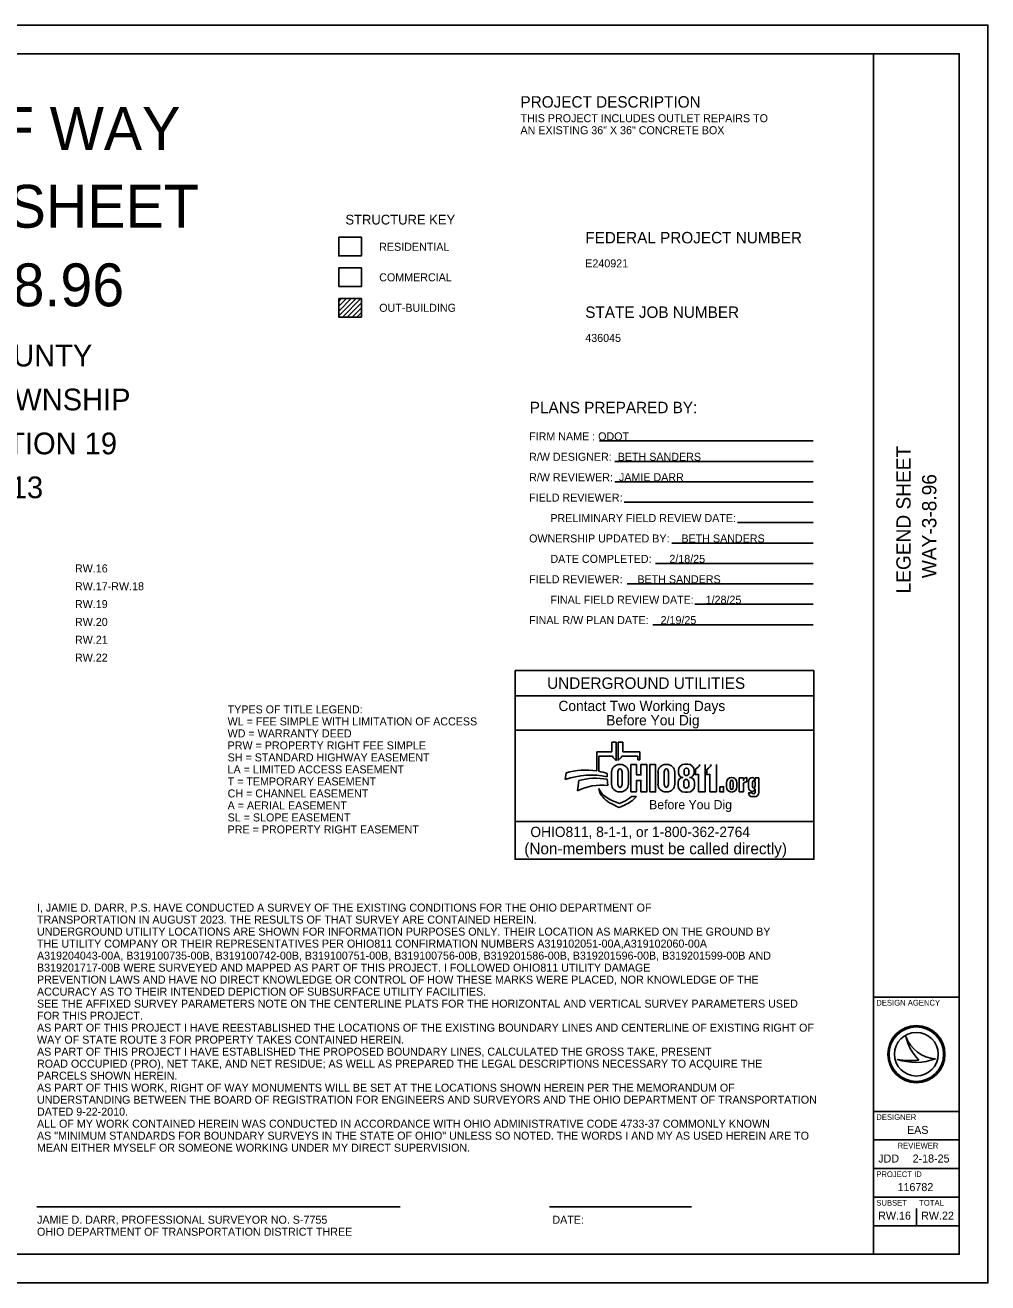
# Model space of a CAD drawing. Extents: x 0 to 34, y 0 to 22.
# Drawn here: x 17.17 to 34, y 0 to 22 of the extents above; entities that cross this region are included whole.
import ezdxf

# ---------------------------------------------------------------- set-up
doc = ezdxf.new("R2010")
doc.units = 0
for name, color, linetype in [('Default', 7, 'Continuous'), ('SC_Shading1', 7, 'Continuous'), ('SH_Border', 7, 'Continuous'), ('SH_Cut_Line', 7, 'Continuous'), ('SH_Data', 7, 'Continuous'), ('SH_Text', 7, 'Continuous')]:
    doc.layers.add(name, color=color, linetype=linetype)

msp = doc.modelspace()

# ---------------------------------------------------------------- linework, layer by layer
at = {"layer": 'Default'}
for p, q in [((17.374, 1.33), (23.727, 1.33)), ((26.334, 1.33), (28.821, 1.33))]:
    msp.add_line(p, q, dxfattribs=at)
at = {"layer": 'SC_Shading1'}
msp.add_lwpolyline([(22.649, 17.428), (23.046, 17.428), (23.046, 17.754), (22.649, 17.754)], close=True, dxfattribs=at)
at = {"layer": 'SH_Border'}
for p, q in [((32, 0.5), (32, 21.5)), ((32, 5), (33.5, 5)), ((32, 3), (33.5, 3)), ((32, 2.5), (33.5, 2.5)), ((32, 2), (33.5, 2)), ((32, 1.5), (33.5, 1.5)), ((32, 1), (33.5, 1))]:
    msp.add_line(p, q, dxfattribs=at)
msp.add_lwpolyline([(1.5, 21.5), (33.5, 21.5), (33.5, 0.5), (1.5, 0.5)], close=True, dxfattribs=at)
at = {"layer": 'SH_Cut_Line'}
msp.add_lwpolyline([(0, 0), (34, 0), (34, 22), (0, 22)], close=True, dxfattribs=at)
at = {"layer": 'SH_Data'}
for p, q in [((27.424, 9.289), (27.161, 9.289)), ((27.161, 9.289), (27.161, 8.954)), ((27.504, 9.455), (27.424, 9.455)), ((27.424, 9.455), (27.424, 9.289)), ((27.504, 9.138), (27.504, 9.455)), ((27.615, 9.455), (27.535, 9.455)), ((27.535, 9.455), (27.535, 9.138)), ((27.615, 9.289), (27.615, 9.455)), ((27.913, 9.289), (27.615, 9.289)), ((27.913, 9.148), (27.913, 9.289)), ((27.198, 8.948), (27.198, 9.212)), ((27.198, 9.212), (27.439, 9.212)), ((27.58, 9.067), (27.556, 9.067)), ((27.599, 9.212), (27.878, 9.212)), ((27.858, 9.066), (27.757, 9.066)), ((27.757, 9.066), (27.757, 8.588)), ((27.878, 9.212), (27.878, 9.148)), ((27.878, 9.148), (27.913, 9.148)), ((28.391, 9.067), (28.366, 9.067)), ((28.752, 9.074), (28.703, 9.074)), ((29.056, 9.066), (29.056, 8.588)), ((29.256, 9.066), (29.256, 8.588)), ((26.626, 8.92), (26.612, 8.803)), ((27.345, 8.852), (27.345, 8.91)), ((27.355, 8.702), (27.345, 8.808)), ((27.422, 8.934), (27.422, 8.722)), ((27.531, 8.739), (27.531, 8.921)), ((27.605, 8.921), (27.605, 8.739)), ((27.714, 8.722), (27.714, 8.934)), ((28.233, 8.934), (28.233, 8.722)), ((28.342, 8.739), (28.342, 8.921)), ((28.416, 8.921), (28.416, 8.739)), ((28.525, 8.722), (28.525, 8.934)), ((28.589, 8.96), (28.589, 8.924)), ((28.688, 8.907), (28.688, 8.965)), ((28.769, 8.965), (28.769, 8.907)), ((28.866, 8.924), (28.866, 8.96)), ((28.889, 8.886), (28.889, 8.987)), ((28.938, 8.588), (28.938, 8.9)), ((29.089, 8.886), (29.089, 8.987)), ((29.138, 8.588), (29.138, 8.9)), ((29.725, 8.831), (29.652, 8.831)), ((29.652, 8.831), (29.652, 8.588)), ((29.725, 8.784), (29.725, 8.831)), ((29.786, 8.839), (29.78, 8.839)), ((29.786, 8.765), (29.786, 8.839)), ((29.929, 8.786), (29.929, 8.833)), ((29.929, 8.833), (29.994, 8.833)), ((29.994, 8.833), (29.994, 8.574)), ((26.846, 8.785), (26.824, 8.605)), ((27.197, 8.648), (27.202, 8.621)), ((27.556, 8.588), (27.58, 8.588)), ((27.757, 8.588), (27.858, 8.588)), ((27.858, 8.588), (27.858, 8.79)), ((28.366, 8.588), (28.391, 8.588)), ((28.584, 8.753), (28.584, 8.703)), ((28.685, 8.694), (28.685, 8.755)), ((28.705, 8.582), (28.751, 8.582)), ((28.77, 8.755), (28.77, 8.694)), ((28.872, 8.703), (28.872, 8.753)), ((29.056, 8.588), (28.938, 8.588)), ((29.256, 8.588), (29.138, 8.588)), ((29.43, 8.679), (29.43, 8.747)), ((29.497, 8.678), (29.497, 8.747)), ((29.545, 8.747), (29.545, 8.678)), ((29.612, 8.747), (29.612, 8.679)), ((29.652, 8.588), (29.725, 8.588)), ((29.725, 8.588), (29.725, 8.715)), ((29.774, 8.765), (29.786, 8.765)), ((29.814, 8.666), (29.814, 8.77)), ((29.886, 8.68), (29.886, 8.756)), ((29.929, 8.756), (29.929, 8.68)), ((29.929, 8.574), (29.929, 8.644)), ((27.562, 8.387), (27.474, 8.418)), ((27.624, 8.414), (27.562, 8.387)), ((27.856, 8.508), (27.77, 8.508)), ((27.853, 8.505), (27.856, 8.508)), ((29.814, 8.574), (29.886, 8.574)), ((29.924, 8.505), (29.884, 8.505)), ((27.498, 8.341), (27.553, 8.317)), ((27.553, 8.317), (27.648, 8.358)), ((30.96, 7.41), (25.735, 7.41)), ((32.567, 4.31), (32.567, 4.31)), ((32.75, 4), (32.75, 4)), ((32.417, 3.91), (32.417, 3.91)), ((33.087, 3.919), (33.087, 3.919)), ((32.75, 1), (32.75, 1.3))]:
    msp.add_line(p, q, dxfattribs=at)
for points in [[(25.735, 10.71), (30.96, 10.71), (30.96, 10.27), (25.735, 10.27)], [(25.735, 10.27), (30.96, 10.27), (30.96, 9.665), (25.735, 9.665)], [(25.735, 9.665), (30.96, 9.665), (30.96, 8.07), (25.735, 8.07)], [(29.314, 8.678), (29.38, 8.678), (29.38, 8.588), (29.314, 8.588)], [(25.735, 8.07), (30.96, 8.07), (30.96, 7.41), (25.735, 7.41)]]:
    msp.add_lwpolyline(points, close=True, dxfattribs=at)
for points in [[(27.858, 8.79), (27.934, 8.79), (27.934, 8.588), (28.036, 8.588), (28.036, 9.066), (27.934, 9.066), (27.934, 8.886), (27.858, 8.886), (27.858, 9.066)], [(28.087, 8.588), (28.189, 8.588), (28.189, 9.066), (28.087, 9.066), (28.087, 8.588)], [(28.67, 8.84), (28.67, 8.84)], [(28.786, 8.84), (28.786, 8.84)]]:
    msp.add_lwpolyline(points, dxfattribs=at)
for radius in [0.5, 0.477, 0.477, 0.382]:
    msp.add_circle((32.75, 4), radius, dxfattribs=at)
for centre, radius, start, end in [((27.556, 8.934), 0.134, 90, 180), ((27.576, 9.267), 0.147, 201.9296, 240.7469), ((27.463, 9.267), 0.147, 299.2531, 338.0704), ((27.58, 8.934), 0.134, 0, 90), ((28.366, 8.934), 0.134, 90, 180), ((28.391, 8.934), 0.134, 0, 90), ((28.703, 8.96), 0.114, 90, 180), ((28.752, 8.96), 0.114, 0, 90), ((28.839, 9.109), 0.132, 292.5572, 340.7355), ((29.039, 9.109), 0.132, 292.5572, 340.7355), ((27.064, 7.55), 1.332, 77.8238, 109.8274), ((26.969, 7.746), 1.224, 81.0007, 106.3144), ((27.145, 7.733), 1.094, 79.44, 105.8467), ((26.969, 7.746), 1.224, 72.1402, 79.2074), ((28.67, 8.753), 0.0865, 90, 180), ((28.673, 8.924), 0.0837, 180, 268.1442), ((28.783, 8.924), 0.0837, 272.2058, 0), ((28.786, 8.753), 0.0865, 0, 90), ((28.877, 9.017), 0.132, 275.1733, 297.0931), ((29.077, 9.017), 0.132, 275.1733, 297.0931), ((29.525, 8.747), 0.0956, 92.5886, 180), ((29.517, 8.747), 0.0956, 0, 87.4114), ((29.78, 8.784), 0.0548, 90, 180), ((29.882, 8.77), 0.0686, 92.6865, 180), ((29.876, 8.786), 0.0524, 0, 86.9262), ((27.253, 7.758), 0.95, 83.8248, 116.8021), ((27.477, 8.756), 0.3, 201.0457, 232.5314), ((27.413, 8.657), 0.214, 189.6817, 216.0884), ((27.556, 8.722), 0.134, 180, 270), ((27.58, 8.722), 0.134, 270, 0), ((28.366, 8.722), 0.134, 180, 270), ((28.391, 8.722), 0.134, 270, 0), ((28.705, 8.703), 0.121, 180, 270), ((28.751, 8.703), 0.121, 270, 0), ((29.525, 8.679), 0.0956, 180, 267.4114), ((29.517, 8.679), 0.0956, 272.5886, 0), ((29.774, 8.715), 0.0493, 90, 180), ((29.883, 8.666), 0.0692, 180, 265.7132), ((29.882, 8.644), 0.0467, 264.7825, 0), ((27.613, 8.803), 0.461, 216.0884, 235.7167), ((27.765, 9.131), 0.773, 232.5314, 241.794), ((27.861, 9.168), 0.903, 235.7167, 246.2325), ((27.638, 8.894), 0.504, 241.794, 250.9821), ((27.41, 8.907), 0.538, 293.4582, 312.0712), ((27.41, 8.907), 0.599, 293.4582, 317.8286), ((29.884, 8.574), 0.0699, 180, 270), ((29.924, 8.574), 0.0699, 270, 0), ((33.116, 4.498), 0.58, 198.9257, 198.9319), ((33.347, 4.47), 0.796, 191.6379, 191.6421), ((33.116, 4.498), 0.58, 198.9319, 267.1657), ((33.347, 4.47), 0.796, 191.6421, 226.0947), ((32.739, 4.87), 1.013, 251.4576, 290.0832), ((32.648, 5.154), 1.266, 259.4964, 259.4995), ((32.739, 4.87), 1.013, 251.4527, 251.4576), ((32.648, 5.154), 1.266, 259.4995, 276.6672)]:
    msp.add_arc(centre, radius, start, end, dxfattribs=at)
for centre, major_axis, ratio, start_param, end_param in [((27.568, 8.921), (0, 0.0723), 0.514403, 4.712389, 7.853982), ((28.379, 8.921), (0, 0.0723), 0.514403, 4.712389, 7.853982), ((28.727, 8.755), (0, 0.0535), 0.794529, 4.712389, 7.853982), ((28.729, 8.965), (0.0404, 0), 0.969373, 0, 3.141593), ((28.729, 8.907), (0.0404, 0), 0.818453, 3.141593, 6.283185), ((27.568, 8.739), (0, 0.0723), 0.514403, 1.570796, 4.712389), ((28.379, 8.739), (0, 0.0723), 0.514403, 1.570796, 4.712389), ((28.727, 8.694), (0.0425, 0), 0.959837, 3.141593, 6.283185), ((29.521, 8.747), (0, 0.0434), 0.553236, 4.712389, 7.853982), ((29.521, 8.678), (0, 0.046), 0.522014, 1.570796, 4.712389), ((29.907, 8.756), (0, 0.0275), 0.777179, 4.712389, 7.853982), ((29.907, 8.68), (0, 0.0275), 0.777179, 1.570796, 4.712389), ((29.907, 8.574), (0.0214, 0), 0.959012, 3.141593, 6.283185)]:
    msp.add_ellipse(centre, major_axis=major_axis, ratio=ratio, start_param=start_param, end_param=end_param, dxfattribs=at)
at = {"layer": 'SH_Text'}
for p, q in [((22.649, 17.217), (22.65, 17.219)), ((22.649, 17.167), (22.701, 17.219)), ((22.649, 17.083), (22.785, 17.219)), ((22.649, 16.998), (22.87, 17.219)), ((22.649, 16.913), (22.955, 17.219)), ((22.713, 16.893), (23.039, 17.219)), ((22.798, 16.893), (23.046, 17.141)), ((22.883, 16.893), (23.046, 17.056)), ((22.968, 16.893), (23.046, 16.971)), ((22.649, 16.897), (22.654, 16.893)), ((27.211, 14.727), (30.948, 14.727)), ((27.475, 14.37), (30.948, 14.37)), ((27.475, 14.013), (30.948, 14.013)), ((27.639, 13.656), (30.948, 13.656)), ((29.621, 13.298), (30.948, 13.298)), ((28.475, 12.941), (30.948, 12.941)), ((28.19, 12.584), (30.948, 12.584)), ((27.693, 12.227), (30.948, 12.227)), ((28.874, 11.87), (30.948, 11.87)), ((28.145, 11.513), (30.948, 11.513))]:
    msp.add_line(p, q, dxfattribs=at)
for points in [[(22.649, 18.289), (23.046, 18.289), (23.046, 17.963), (22.649, 17.963)], [(22.649, 17.219), (23.046, 17.219), (23.046, 16.893), (22.649, 16.893)]]:
    msp.add_lwpolyline(points, close=True, dxfattribs=at)

# ---------------------------------------------------------------- texts
at = {"layer": 'Default'}
for s, p in [('I, JAMIE D. DARR, P.S. HAVE CONDUCTED A SURVEY OF THE EXISTING CONDITIONS FOR THE OHIO DEPARTMENT OF', (17.374, 6.494)), ('TRANSPORTATION IN AUGUST 2023. THE RESULTS OF THAT SURVEY ARE CONTAINED HEREIN.', (17.374, 6.284)), ('UNDERGROUND UTILITY LOCATIONS ARE SHOWN FOR INFORMATION PURPOSES ONLY. THEIR LOCATION AS MARKED ON THE GROUND BY ', (17.374, 6.074)), ('THE UTILITY COMPANY OR THEIR REPRESENTATIVES PER OHIO811 CONFIRMATION NUMBERS A319102051-00A,A319102060-00A', (17.374, 5.864)), ('A319204043-00A, B319100735-00B, B319100742-00B, B319100751-00B, B319100756-00B, B319201586-00B, B319201596-00B, B319201599-00B AND', (17.374, 5.654)), ('B319201717-00B WERE SURVEYED AND MAPPED AS PART OF THIS PROJECT. I FOLLOWED OHIO811 UTILITY DAMAGE', (17.374, 5.444)), ('PREVENTION LAWS AND HAVE NO DIRECT KNOWLEDGE OR CONTROL OF HOW THESE MARKS WERE PLACED, NOR KNOWLEDGE OF THE ', (17.374, 5.234)), ('ACCURACY AS TO THEIR INTENDED DEPICTION OF SUBSURFACE UTILITY FACILITIES.', (17.374, 5.024)), ('SEE THE AFFIXED SURVEY PARAMETERS NOTE ON THE CENTERLINE PLATS FOR THE HORIZONTAL AND VERTICAL SURVEY PARAMETERS USED ', (17.374, 4.814)), ('FOR THIS PROJECT.', (17.374, 4.604)), ('AS PART OF THIS PROJECT I HAVE REESTABLISHED THE LOCATIONS OF THE EXISTING BOUNDARY LINES AND CENTERLINE OF EXISTING RIGHT OF ', (17.374, 4.394)), ('WAY OF STATE ROUTE 3 FOR PROPERTY TAKES CONTAINED HEREIN.', (17.374, 4.184)), ('AS PART OF THIS PROJECT I HAVE ESTABLISHED THE PROPOSED BOUNDARY LINES, CALCULATED THE GROSS TAKE, PRESENT', (17.374, 3.974)), ('ROAD OCCUPIED (PRO), NET TAKE, AND NET RESIDUE; AS WELL AS PREPARED THE LEGAL DESCRIPTIONS NECESSARY TO ACQUIRE THE', (17.374, 3.764)), ('PARCELS SHOWN HEREIN.', (17.374, 3.554)), ('AS PART OF THIS WORK, RIGHT OF WAY MONUMENTS WILL BE SET AT THE LOCATIONS SHOWN HEREIN PER THE MEMORANDUM OF ', (17.374, 3.344)), ('UNDERSTANDING BETWEEN THE BOARD OF REGISTRATION FOR ENGINEERS AND SURVEYORS AND THE OHIO DEPARTMENT OF TRANSPORTATION ', (17.374, 3.134)), ('DATED 9-22-2010.', (17.374, 2.924)), ('ALL OF MY WORK CONTAINED HEREIN WAS CONDUCTED IN ACCORDANCE WITH OHIO ADMINISTRATIVE CODE 4733-37 COMMONLY KNOWN', (17.374, 2.714)), ('AS "MINIMUM STANDARDS FOR BOUNDARY SURVEYS IN THE STATE OF OHIO" UNLESS SO NOTED. THE WORDS I AND MY AS USED HEREIN ARE TO', (17.374, 2.504)), ('MEAN EITHER MYSELF OR SOMEONE WORKING UNDER MY DIRECT SUPERVISION.', (17.374, 2.294)), ('JAMIE D. DARR, PROFESSIONAL SURVEYOR NO. S-7755                                                               ', (17.374, 1.034)), (' DATE:', (26.334, 1.034)), ('OHIO DEPARTMENT OF TRANSPORTATION DISTRICT THREE', (17.374, 0.824))]:
    msp.add_text(s, height=0.14, dxfattribs=at).set_placement(p)
at = {"layer": 'SH_Data'}
for s, height, p in [('RIGHT OF WAY', 0.75, (12.527, 19.816)), ('LEGEND SHEET', 0.75, (12.458, 18.457)), ('  WAY-3-8.96 ', 0.75, (12.879, 17.082)), ('      WAYNE COUNTY     ', 0.38, (13.343, 16.03)), ('    WOOSTER TOWNSHIP   ', 0.38, (12.94, 15.262)), ('   SW QTR SECTION 19   ', 0.38, (13.211, 14.493)), ('      T. 15, R. 13     ', 0.38, (13.979, 13.725)), ('RW.16 ', 0.14, (18.038, 12.427)), ('RW.17-RW.18', 0.14, (18.038, 12.115)), ('RW.19 ', 0.14, (18.038, 11.803)), ('RW.20 ', 0.14, (18.038, 11.491)), ('RW.21 ', 0.14, (18.038, 11.179)), ('RW.22 ', 0.14, (18.038, 10.867)), ('UNDERGROUND UTILITIES', 0.2, (26.294, 10.39)), ('Contact Two Working Days', 0.18, (26.492, 10.002)), ('Before You Dig', 0.18, (27.327, 9.752)), ('Before You Dig', 0.15972, (28.078, 8.285)), ('OHIO811, 8-1-1, or 1-800-362-2764', 0.18, (26.001, 7.798)), ('(Non-members must be called directly)', 0.2, (25.895, 7.497)), ('DESIGN AGENCY', 0.1, (32.05, 4.85)), ('DESIGNER', 0.1, (32.05, 2.85)), ('EAS', 0.14, (32.587, 2.605)), ('REVIEWER', 0.1, (32.422, 2.35)), ('JDD', 0.14, (32.084, 2.105)), ('2-18-25', 0.14, (32.685, 2.105)), ('PROJECT ID', 0.1, (32.05, 1.85)), ('116782', 0.14, (32.421, 1.605)), ('SUBSET', 0.1, (32.05, 1.35)), ('TOTAL', 0.1, (32.8, 1.35)), ('RW.16', 0.14, (32.083, 1.105)), ('RW.22', 0.14, (32.834, 1.105))]:
    msp.add_text(s, height=height, dxfattribs=at).set_placement(p)
for s, p in [('LEGEND SHEET', (32.65, 12.06)), ('WAY-3-8.96', (33.1, 12.326))]:
    msp.add_text(s, height=0.25, rotation=90, dxfattribs=at).set_placement(p)
at = {"layer": 'SH_Text'}
for s, height, p in [('PROJECT DESCRIPTION', 0.2, (25.828, 20.557)), ('THIS PROJECT INCLUDES OUTLET REPAIRS TO', 0.14, (25.828, 20.302)), ('AN EXISTING 36" X 36" CONCRETE BOX', 0.14, (25.828, 20.092)), ('STRUCTURE KEY', 0.17, (22.767, 18.513)), ('FEDERAL PROJECT NUMBER', 0.2, (26.961, 18.183)), ('RESIDENTIAL', 0.14, (23.358, 18.053)), ('E240921   ', 0.14, (26.961, 17.763)), ('COMMERCIAL', 0.14, (23.358, 17.519)), ('OUT-BUILDING', 0.14, (23.358, 16.986)), ('STATE JOB NUMBER', 0.2, (26.961, 16.879)), ('436045    ', 0.14, (26.961, 16.459)), ('PLANS PREPARED BY:', 0.2, (25.991, 15.212)), ('FIRM NAME : ODOT', 0.14, (25.979, 14.737)), ('R/W DESIGNER:  BETH SANDERS', 0.14, (25.979, 14.38)), ('R/W REVIEWER:  JAMIE DARR', 0.14, (25.979, 14.023)), ('FIELD REVIEWER:', 0.14, (25.979, 13.666)), ('PRELIMINARY FIELD REVIEW DATE:', 0.14, (26.351, 13.308)), ('OWNERSHIP UPDATED BY:    BETH SANDERS', 0.14, (25.979, 12.951)), ('DATE COMPLETED:      2/18/25', 0.14, (26.351, 12.594)), ('FIELD REVIEWER:     BETH SANDERS', 0.14, (25.979, 12.237)), ('FINAL FIELD REVIEW DATE:    1/28/25', 0.14, (26.351, 11.879)), ('FINAL R/W PLAN DATE:    2/19/25', 0.14, (25.979, 11.523)), ('TYPES OF TITLE LEGEND:', 0.14, (20.707, 9.961)), ('WL = FEE SIMPLE WITH LIMITATION OF ACCESS', 0.14, (20.707, 9.751)), ('WD = WARRANTY DEED', 0.14, (20.707, 9.541)), ('PRW = PROPERTY RIGHT FEE SIMPLE', 0.14, (20.707, 9.331)), ('SH = STANDARD HIGHWAY EASEMENT', 0.14, (20.707, 9.121)), ('LA = LIMITED ACCESS EASEMENT', 0.14, (20.707, 8.911)), ('T = TEMPORARY EASEMENT', 0.14, (20.707, 8.701)), ('CH = CHANNEL EASEMENT', 0.14, (20.707, 8.491)), ('A = AERIAL EASEMENT', 0.14, (20.707, 8.281)), ('SL = SLOPE EASEMENT', 0.14, (20.707, 8.071)), ('PRE = PROPERTY RIGHT EASEMENT', 0.14, (20.707, 7.861))]:
    msp.add_text(s, height=height, dxfattribs=at).set_placement(p)

doc.saveas('drawing.dxf')
